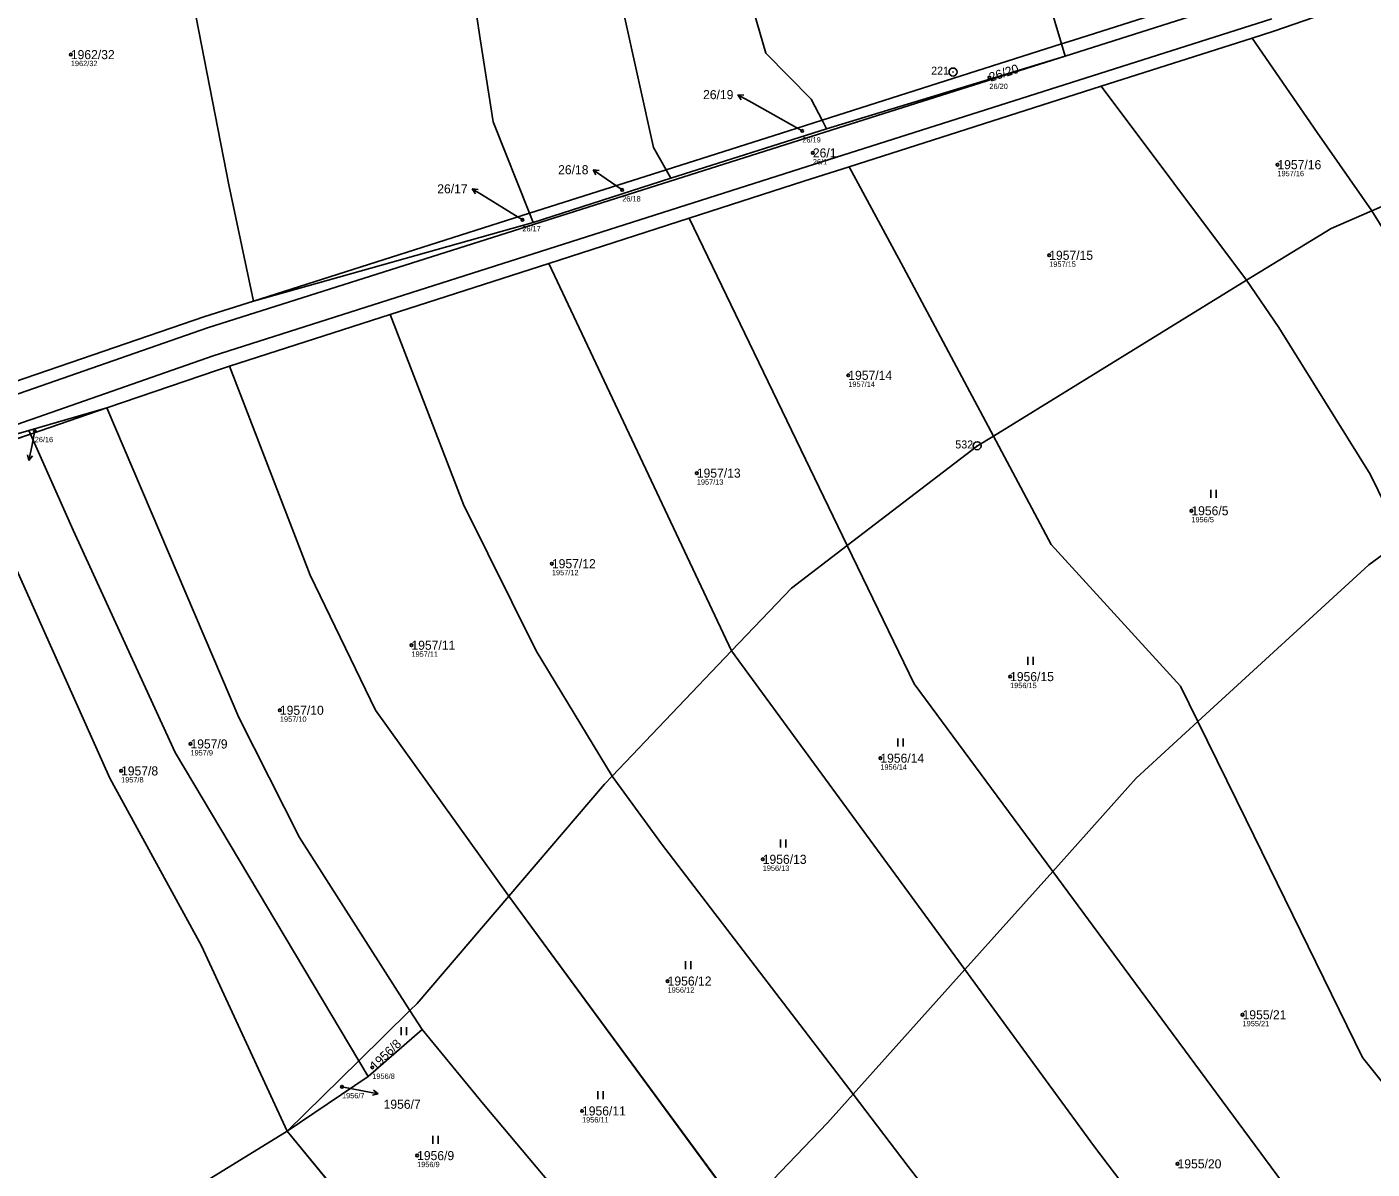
# Model space of a CAD drawing. Extents: x -762274 to -759271, y -1061928 to -1059060.
# Drawn here: x -761526.6 to -761274.4, y -1060598 to -1060383.9 of the extents above; entities that cross this region are included whole.
import ezdxf

# ---------------------------------------------------------------- set-up
doc = ezdxf.new("R2010")
doc.units = 0
for name, color, linetype in [('Definiční body', 7, 'Continuous'), ('Hranice parcel', 7, 'Continuous'), ('Parcelní čísla', 7, 'Continuous'), ('Polygon ku', 7, 'Continuous'), ('Polygon parcely', 7, 'Continuous'), ('Pop  PČ popisy', 7, 'Continuous'), ('Vnitřní kresba', 7, 'Continuous'), ('Značky bodu BP', 7, 'Continuous'), ('Značky kultur', 7, 'Continuous')]:
    doc.layers.add(name, color=color, linetype=linetype)

msp = doc.modelspace()

# ---------------------------------------------------------------- linework, layer by layer
at = {"layer": 'Definiční body'}
for centre in [(-761518.34, -1060389.11), (-761346.14, -1060393.4), (-761381.21, -1060403.42), (-761379.23, -1060407.54), (-761292.14, -1060409.74), (-761414.97, -1060414.48), (-761433.7, -1060420.09), (-761334.92, -1060426.73), (-761372.59, -1060449.23), (-761525.12, -1060459.6), (-761400.99, -1060467.56), (-761308.27, -1060474.62), (-761428.15, -1060484.54), (-761454.49, -1060499.83), (-761342.26, -1060505.71), (-761479.15, -1060512.02), (-761495.92, -1060518.33), (-761366.58, -1060521), (-761508.93, -1060523.39), (-761388.63, -1060539.96), (-761406.46, -1060562.78), (-761298.67, -1060569.1), (-761461.83, -1060578.96), (-761467.51, -1060582.6), (-761422.51, -1060587.13), (-761453.43, -1060595.5), (-761310.86, -1060597.04)]:
    msp.add_circle(centre, 0.25, dxfattribs=at)
at = {"layer": 'Hranice parcel'}
for p, q in [((-761325.18, -1060395.04), (-761296.86, -1060386)), ((-761332.64, -1060387.09), (-761377.52, -1060401.4)), ((-761372.45, -1060410.13), (-761325.18, -1060395.04)), ((-761297.91, -1060431.42), (-761325.18, -1060395.04)), ((-761376.68, -1060403.03), (-761377.52, -1060401.4)), ((-761376.68, -1060403.03), (-761405.87, -1060412.27)), ((-761246.84, -1060406.46), (-761274.47, -1060418.39)), ((-761406.76, -1060410.7), (-761432.38, -1060418.84)), ((-761405.87, -1060412.27), (-761406.76, -1060410.7)), ((-761405.87, -1060412.27), (-761431.68, -1060420.61)), ((-761432.38, -1060418.84), (-761484.13, -1060435.3)), ((-761431.68, -1060420.61), (-761432.38, -1060418.84)), ((-761431.68, -1060420.61), (-761484.13, -1060435.3)), ((-761428.73, -1060428.24), (-761402.43, -1060419.76)), ((-761372.78, -1060481.11), (-761402.43, -1060419.76)), ((-761458.5, -1060437.83), (-761428.73, -1060428.24)), ((-761394.5, -1060500.9), (-761428.73, -1060428.24)), ((-761297.91, -1060431.42), (-761345.39, -1060460.62)), ((-761488.58, -1060447.52), (-761458.5, -1060437.83)), ((-761526.19, -1060459.55), (-761511.57, -1060455.34)), ((-761525.89, -1060460.23), (-761511.57, -1060455.34)), ((-761538.67, -1060463.15), (-761526.19, -1060459.55)), ((-761525.89, -1060460.23), (-761526.19, -1060459.55)), ((-761538.1, -1060464.41), (-761525.89, -1060460.23)), ((-761394.5, -1060500.9), (-761416.86, -1060524.35)), ((-761334.27, -1060542.22), (-761350.76, -1060560.62)), ((-761392.63, -1060606.18), (-761436.24, -1060546.87)), ((-761350.76, -1060560.62), (-761371.7, -1060584)), ((-761454.77, -1060568.31), (-761464.35, -1060577.72)), ((-761452.51, -1060571.84), (-761454.77, -1060568.31)), ((-761462.59, -1060580.67), (-761452.51, -1060571.84)), ((-761464.35, -1060577.72), (-761477.78, -1060590.89)), ((-761462.59, -1060580.67), (-761464.35, -1060577.72)), ((-761477.78, -1060590.89), (-761462.59, -1060580.67)), ((-761523, -1060618.75), (-761477.78, -1060590.89)), ((-761477.78, -1060590.89), (-761452.75, -1060621.37))]:
    msp.add_line(p, q, dxfattribs=at)
for points in [[(-761362.61, -1060303.98), (-761337.24, -1060371.56), (-761332.64, -1060387.09)], [(-761377.52, -1060401.4), (-761379.53, -1060397.49), (-761388.03, -1060388.82), (-761399.3, -1060350.06), (-761408.95, -1060318.37)], [(-761406.76, -1060410.7), (-761409.13, -1060406.55), (-761417.69, -1060367.87), (-761425.29, -1060334.5), (-761428.3, -1060320.92)], [(-761484.13, -1060435.3), (-761488.72, -1060413.55), (-761499.47, -1060358.42), (-761505.75, -1060325.72)], [(-761432.38, -1060418.84), (-761439.17, -1060401.68), (-761441.59, -1060386.18), (-761450.25, -1060328.82), (-761451.14, -1060325.88)], [(-761332.64, -1060387.09), (-761330.38, -1060386.37), (-761302.61, -1060377.52)], [(-761296.86, -1060386), (-761292.81, -1060384.71), (-761272.53, -1060377.65)], [(-761274.47, -1060418.39), (-761284.66, -1060403.7), (-761296.86, -1060386)], [(-761332.64, -1060387.09), (-761331.96, -1060389.38), (-761376.68, -1060403.03)], [(-761377.52, -1060401.4), (-761383.76, -1060403.39), (-761406.76, -1060410.7)], [(-761402.43, -1060419.76), (-761380.95, -1060412.84), (-761372.45, -1060410.13)], [(-761345.39, -1060460.62), (-761362.25, -1060429), (-761372.45, -1060410.13)], [(-761274.47, -1060418.39), (-761282.08, -1060421.68), (-761297.91, -1060431.42)], [(-761246.65, -1060463.98), (-761253.69, -1060451.75), (-761274.47, -1060418.39)], [(-761268.68, -1060480.14), (-761274.76, -1060467.77), (-761291.87, -1060440.27), (-761297.91, -1060431.42)], [(-761484.13, -1060435.3), (-761493.24, -1060438.19), (-761531.09, -1060451.17)], [(-761416.86, -1060524.35), (-761431.13, -1060500.87), (-761444.7, -1060473.47), (-761458.5, -1060437.83)], [(-761511.57, -1060455.34), (-761490.88, -1060448.26), (-761488.58, -1060447.52)], [(-761436.24, -1060546.87), (-761461.2, -1060512.01), (-761473.48, -1060486.69), (-761488.58, -1060447.52)], [(-761454.77, -1060568.31), (-761475.49, -1060535.88), (-761486.82, -1060513.35), (-761511.57, -1060455.34)], [(-761464.35, -1060577.72), (-761498.76, -1060519.96), (-761517.93, -1060478.26), (-761525.89, -1060460.23)], [(-761345.39, -1060460.62), (-761348.35, -1060462.44), (-761372.78, -1060481.11)], [(-761345.39, -1060460.62), (-761334.54, -1060480.95), (-761310.32, -1060507.49), (-761307.05, -1060514.14)], [(-761477.78, -1060590.89), (-761493.84, -1060556.2), (-761511.02, -1060524.76), (-761538.1, -1060464.41)], [(-761372.78, -1060481.11), (-761383.26, -1060489.11), (-761394.5, -1060500.9)], [(-761334.27, -1060542.22), (-761360.24, -1060507.07), (-761372.78, -1060481.11)], [(-761268.68, -1060480.14), (-761275.01, -1060484.78), (-761307.05, -1060514.14)], [(-761350.76, -1060560.62), (-761361.3, -1060546.19), (-761394.5, -1060500.9)], [(-761307.05, -1060514.14), (-761318.62, -1060524.75), (-761334.27, -1060542.22)], [(-761307.05, -1060514.14), (-761298.01, -1060532.54), (-761276.2, -1060577.12), (-761265.28, -1060590.77), (-761260.39, -1060596.89)], [(-761416.86, -1060524.35), (-761418.28, -1060525.85), (-761436.24, -1060546.87)], [(-761371.7, -1060584), (-761407.62, -1060537.03), (-761416.86, -1060524.35)], [(-761276.17, -1060617.86), (-761288.21, -1060604.6), (-761320.85, -1060560.37), (-761334.27, -1060542.22)], [(-761436.24, -1060546.87), (-761453.44, -1060567.01), (-761454.77, -1060568.31)], [(-761291.07, -1060637.45), (-761301.57, -1060626.62), (-761326.45, -1060593.88), (-761350.76, -1060560.62)], [(-761427.51, -1060601.89), (-761440.98, -1060585.86), (-761452.51, -1060571.84)], [(-761371.7, -1060584), (-761376.48, -1060589.33), (-761392.63, -1060606.18)], [(-761310.57, -1060663.1), (-761361.34, -1060597.55), (-761371.7, -1060584)]]:
    msp.add_lwpolyline(points, dxfattribs=at)
at = {"layer": 'Polygon ku'}
msp.add_lwpolyline([(-761842.98, -1060551.47), (-761837.25, -1060550.74), (-761825.78, -1060549.27), (-761803.29, -1060543.28), (-761774.98, -1060535.73), (-761709.41, -1060525.13), (-761690.07, -1060520.8), (-761668.95, -1060513.73), (-761597.93, -1060485.6), (-761588.44, -1060482.32), (-761523.76, -1060617.27), (-761523, -1060618.75), (-761477.78, -1060590.89), (-761452.75, -1060621.37), (-761435.65, -1060642.18), (-761397.03, -1060689.2), (-761389.24, -1060698.69), (-761426.21, -1060752.67)], dxfattribs=at)
at = {"layer": 'Polygon parcely'}
for points in [[(-761302.61, -1060377.52), (-761335.24, -1060297.31), (-761362.61, -1060303.98), (-761337.24, -1060371.56), (-761332.64, -1060387.09), (-761330.38, -1060386.37)], [(-761362.61, -1060303.98), (-761409.45, -1060315.4), (-761408.95, -1060318.37), (-761399.3, -1060350.06), (-761388.03, -1060388.82), (-761379.53, -1060397.49), (-761377.52, -1060401.4), (-761332.64, -1060387.09), (-761337.24, -1060371.56)], [(-761420.69, -1060318.65), (-761428.3, -1060320.92), (-761425.29, -1060334.5), (-761417.69, -1060367.87), (-761409.13, -1060406.55), (-761406.76, -1060410.7), (-761383.76, -1060403.39), (-761377.52, -1060401.4), (-761379.53, -1060397.49), (-761388.03, -1060388.82), (-761399.3, -1060350.06), (-761408.95, -1060318.37)], [(-761417.69, -1060367.87), (-761425.29, -1060334.5), (-761428.3, -1060320.92), (-761434.1, -1060322.65), (-761451.14, -1060325.88), (-761450.25, -1060328.82), (-761441.59, -1060386.18), (-761439.17, -1060401.68), (-761432.38, -1060418.84), (-761406.76, -1060410.7), (-761409.13, -1060406.55)], [(-761488.72, -1060413.55), (-761499.47, -1060358.42), (-761505.75, -1060325.72), (-761506.39, -1060325.86), (-761554.18, -1060336.81), (-761542.84, -1060392.48), (-761531.09, -1060451.17), (-761493.24, -1060438.19), (-761484.13, -1060435.3)], [(-761498.72, -1060324.18), (-761505.75, -1060325.72), (-761499.47, -1060358.42), (-761488.72, -1060413.55), (-761484.13, -1060435.3), (-761432.38, -1060418.84), (-761439.17, -1060401.68), (-761441.59, -1060386.18), (-761450.25, -1060328.82), (-761451.14, -1060325.88), (-761468.12, -1060329.09), (-761491.54, -1060327.88)], [(-761246.84, -1060406.46), (-761272.53, -1060377.65), (-761292.81, -1060384.71), (-761296.86, -1060386), (-761284.66, -1060403.7), (-761274.47, -1060418.39)], [(-761284.66, -1060403.7), (-761296.86, -1060386), (-761325.18, -1060395.04), (-761297.91, -1060431.42), (-761282.08, -1060421.68), (-761274.47, -1060418.39)], [(-761332.64, -1060387.09), (-761377.52, -1060401.4), (-761376.68, -1060403.03), (-761331.96, -1060389.38)], [(-761297.91, -1060431.42), (-761325.18, -1060395.04), (-761372.45, -1060410.13), (-761362.25, -1060429), (-761345.39, -1060460.62)], [(-761406.76, -1060410.7), (-761405.87, -1060412.27), (-761376.68, -1060403.03), (-761377.52, -1060401.4), (-761383.76, -1060403.39)], [(-761244.63, -1060409.46), (-761246.84, -1060406.46), (-761274.47, -1060418.39), (-761253.69, -1060451.75), (-761246.65, -1060463.98), (-761233.1, -1060454.04), (-761223.06, -1060446.53), (-761227.26, -1060439)], [(-761405.87, -1060412.27), (-761406.76, -1060410.7), (-761432.38, -1060418.84), (-761431.68, -1060420.61)], [(-761362.25, -1060429), (-761372.45, -1060410.13), (-761380.95, -1060412.84), (-761402.43, -1060419.76), (-761372.78, -1060481.11), (-761348.35, -1060462.44), (-761345.39, -1060460.62)], [(-761431.68, -1060420.61), (-761432.38, -1060418.84), (-761484.13, -1060435.3)], [(-761282.08, -1060421.68), (-761297.91, -1060431.42), (-761291.87, -1060440.27), (-761274.76, -1060467.77), (-761268.68, -1060480.14), (-761246.65, -1060463.98), (-761253.69, -1060451.75), (-761274.47, -1060418.39)], [(-761372.78, -1060481.11), (-761402.43, -1060419.76), (-761428.73, -1060428.24), (-761394.5, -1060500.9), (-761383.26, -1060489.11)], [(-761394.5, -1060500.9), (-761428.73, -1060428.24), (-761458.5, -1060437.83), (-761444.7, -1060473.47), (-761431.13, -1060500.87), (-761416.86, -1060524.35)], [(-761291.87, -1060440.27), (-761297.91, -1060431.42), (-761345.39, -1060460.62), (-761334.54, -1060480.95), (-761310.32, -1060507.49), (-761307.05, -1060514.14), (-761275.01, -1060484.78), (-761268.68, -1060480.14), (-761274.76, -1060467.77)], [(-761444.7, -1060473.47), (-761458.5, -1060437.83), (-761488.58, -1060447.52), (-761473.48, -1060486.69), (-761461.2, -1060512.01), (-761436.24, -1060546.87), (-761418.28, -1060525.85), (-761416.86, -1060524.35), (-761431.13, -1060500.87)], [(-761473.48, -1060486.69), (-761488.58, -1060447.52), (-761490.88, -1060448.26), (-761511.57, -1060455.34), (-761486.82, -1060513.35), (-761475.49, -1060535.88), (-761454.77, -1060568.31), (-761453.44, -1060567.01), (-761436.24, -1060546.87), (-761461.2, -1060512.01)], [(-761525.89, -1060460.23), (-761511.57, -1060455.34), (-761526.19, -1060459.55)], [(-761486.82, -1060513.35), (-761511.57, -1060455.34), (-761525.89, -1060460.23), (-761517.93, -1060478.26), (-761498.76, -1060519.96), (-761464.35, -1060577.72), (-761454.77, -1060568.31), (-761475.49, -1060535.88)], [(-761525.89, -1060460.23), (-761526.19, -1060459.55), (-761538.67, -1060463.15), (-761538.1, -1060464.41)], [(-761464.35, -1060577.72), (-761498.76, -1060519.96), (-761517.93, -1060478.26), (-761525.89, -1060460.23), (-761538.1, -1060464.41), (-761511.02, -1060524.76), (-761493.84, -1060556.2), (-761477.78, -1060590.89)], [(-761348.35, -1060462.44), (-761372.78, -1060481.11), (-761360.24, -1060507.07), (-761334.27, -1060542.22), (-761318.62, -1060524.75), (-761307.05, -1060514.14), (-761310.32, -1060507.49), (-761334.54, -1060480.95), (-761345.39, -1060460.62)], [(-761538.1, -1060464.41), (-761588.44, -1060482.32), (-761523.76, -1060617.27), (-761523, -1060618.75), (-761477.78, -1060590.89), (-761493.84, -1060556.2), (-761511.02, -1060524.76)], [(-761372.78, -1060481.11), (-761383.26, -1060489.11), (-761394.5, -1060500.9), (-761361.3, -1060546.19), (-761350.76, -1060560.62), (-761334.27, -1060542.22), (-761360.24, -1060507.07)], [(-761275.01, -1060484.78), (-761307.05, -1060514.14), (-761298.01, -1060532.54), (-761276.2, -1060577.12), (-761265.28, -1060590.77), (-761260.39, -1060596.89), (-761255.2, -1060589.71), (-761237.66, -1060565.46), (-761225.6, -1060549.42), (-761225.97, -1060548.93), (-761231.12, -1060542.2), (-761250.91, -1060516.32), (-761268.68, -1060480.14)], [(-761350.76, -1060560.62), (-761361.3, -1060546.19), (-761394.5, -1060500.9), (-761416.86, -1060524.35), (-761407.62, -1060537.03), (-761371.7, -1060584)], [(-761307.05, -1060514.14), (-761318.62, -1060524.75), (-761334.27, -1060542.22), (-761320.85, -1060560.37), (-761288.21, -1060604.6), (-761276.17, -1060617.86), (-761263.67, -1060601.42), (-761260.39, -1060596.89), (-761265.28, -1060590.77), (-761276.2, -1060577.12), (-761298.01, -1060532.54)], [(-761407.62, -1060537.03), (-761416.86, -1060524.35), (-761418.28, -1060525.85), (-761436.24, -1060546.87), (-761392.63, -1060606.18), (-761376.48, -1060589.33), (-761371.7, -1060584)], [(-761288.21, -1060604.6), (-761320.85, -1060560.37), (-761334.27, -1060542.22), (-761350.76, -1060560.62), (-761326.45, -1060593.88), (-761301.57, -1060626.62), (-761291.07, -1060637.45), (-761276.17, -1060617.86)], [(-761392.63, -1060606.18), (-761436.24, -1060546.87), (-761453.44, -1060567.01), (-761454.77, -1060568.31), (-761452.51, -1060571.84), (-761440.98, -1060585.86), (-761427.51, -1060601.89), (-761413.8, -1060619.29), (-761410.99, -1060616.34), (-761407.19, -1060621.37)], [(-761301.57, -1060626.62), (-761326.45, -1060593.88), (-761350.76, -1060560.62), (-761371.7, -1060584), (-761361.34, -1060597.55), (-761310.57, -1060663.1), (-761291.07, -1060637.45)], [(-761452.51, -1060571.84), (-761454.77, -1060568.31), (-761464.35, -1060577.72), (-761462.59, -1060580.67)], [(-761427.51, -1060601.89), (-761440.98, -1060585.86), (-761452.51, -1060571.84), (-761462.59, -1060580.67), (-761477.78, -1060590.89), (-761452.75, -1060621.37), (-761441.29, -1060612.4)], [(-761477.78, -1060590.89), (-761462.59, -1060580.67), (-761464.35, -1060577.72)], [(-761310.57, -1060663.1), (-761361.34, -1060597.55), (-761371.7, -1060584), (-761376.48, -1060589.33), (-761392.63, -1060606.18), (-761382.97, -1060619.31), (-761367.23, -1060640.12), (-761360.72, -1060649.59), (-761330.89, -1060689.83)]]:
    msp.add_lwpolyline(points, close=True, dxfattribs=at)
for points in [[(-761265.99, -1060363.35), (-761276.22, -1060367.49), (-761295.12, -1060375.14), (-761302.61, -1060377.52), (-761330.38, -1060386.37), (-761332.64, -1060387.09), (-761331.96, -1060389.38), (-761376.68, -1060403.03), (-761405.87, -1060412.27), (-761431.68, -1060420.61), (-761484.13, -1060435.3), (-761493.24, -1060438.19), (-761531.09, -1060451.17), (-761592.93, -1060472.36), (-761592.35, -1060473.68), (-761591.85, -1060474.8), (-761590.47, -1060477.92)], [(-761538.67, -1060463.15), (-761526.19, -1060459.55), (-761511.57, -1060455.34), (-761490.88, -1060448.26), (-761488.58, -1060447.52), (-761458.5, -1060437.83), (-761428.73, -1060428.24), (-761402.43, -1060419.76), (-761380.95, -1060412.84), (-761372.45, -1060410.13), (-761325.18, -1060395.04), (-761296.86, -1060386), (-761292.81, -1060384.71), (-761272.53, -1060377.65)]]:
    msp.add_lwpolyline(points, dxfattribs=at)
at = {"layer": 'Pop  PČ popisy'}
for p, q in [((-761390.66, -1060398.09), (-761393.29, -1060396.64)), ((-761393.29, -1060396.64), (-761392.17, -1060396.68)), ((-761393.29, -1060396.64), (-761392.65, -1060397.56)), ((-761381.21, -1060403.42), (-761390.66, -1060398.09)), ((-761417.97, -1060412.4), (-761420.43, -1060410.68)), ((-761420.43, -1060410.68), (-761419.32, -1060410.84)), ((-761420.43, -1060410.68), (-761419.9, -1060411.66)), ((-761440.55, -1060415.85), (-761443.09, -1060414.26)), ((-761443.09, -1060414.26), (-761441.98, -1060414.37)), ((-761443.09, -1060414.26), (-761442.51, -1060415.22)), ((-761414.97, -1060414.48), (-761417.97, -1060412.4)), ((-761433.7, -1060420.09), (-761440.55, -1060415.85)), ((-761525.12, -1060459.6), (-761525.62, -1060462.26)), ((-761525.62, -1060462.26), (-761526.19, -1060465.21)), ((-761526.19, -1060465.21), (-761526.49, -1060464.13)), ((-761526.19, -1060465.21), (-761525.51, -1060464.32)), ((-761467.51, -1060582.6), (-761463.66, -1060583.33)), ((-761463.66, -1060583.33), (-761460.71, -1060583.9)), ((-761460.71, -1060583.9), (-761461.6, -1060583.22)), ((-761460.71, -1060583.9), (-761461.79, -1060584.2))]:
    msp.add_line(p, q, dxfattribs=at)
at = {"layer": 'Vnitřní kresba'}
for p, q in [((-761331.96, -1060389.38), (-761294.41, -1060377.47)), ((-761293.2, -1060382.38), (-761381.7, -1060410.53)), ((-761383.09, -1060405.6), (-761331.96, -1060389.38)), ((-761492.71, -1060440.31), (-761383.09, -1060405.6)), ((-761381.7, -1060410.53), (-761491.65, -1060445.55)), ((-761591.85, -1060474.8), (-761492.71, -1060440.31)), ((-761556.15, -1060468.14), (-761491.65, -1060445.55))]:
    msp.add_line(p, q, dxfattribs=at)
at = {"layer": 'Značky bodu BP'}
for centre, radius in [((-761352.96, -1060392.37), 0.75), ((-761352.96, -1060392.37), 0.03), ((-761348.43, -1060462.44), 0.75), ((-761348.43, -1060462.44), 0.03)]:
    msp.add_circle(centre, radius, dxfattribs=at)
at = {"layer": 'Značky kultur'}
for p, q in [((-761304.64, -1060472.19), (-761304.64, -1060470.69)), ((-761303.64, -1060472.19), (-761303.64, -1060470.69)), ((-761338.96, -1060503.51), (-761338.96, -1060502.01)), ((-761337.96, -1060503.51), (-761337.96, -1060502.01)), ((-761363.32, -1060518.8), (-761363.32, -1060517.3)), ((-761362.32, -1060518.8), (-761362.32, -1060517.3)), ((-761385.29, -1060537.76), (-761385.29, -1060536.26)), ((-761384.29, -1060537.76), (-761384.29, -1060536.26)), ((-761403.13, -1060560.58), (-761403.13, -1060559.08)), ((-761402.13, -1060560.58), (-761402.13, -1060559.08)), ((-761456.43, -1060572.94), (-761456.43, -1060571.44)), ((-761455.43, -1060572.94), (-761455.43, -1060571.44)), ((-761419.56, -1060584.93), (-761419.56, -1060583.43)), ((-761418.56, -1060584.93), (-761418.56, -1060583.43)), ((-761450.47, -1060593.3), (-761450.47, -1060591.8)), ((-761449.47, -1060593.3), (-761449.47, -1060591.8))]:
    msp.add_line(p, q, dxfattribs=at)

# ---------------------------------------------------------------- texts
at = {"layer": 'Definiční body'}
for s, p in [('1962/32', (-761518.34, -1060391.27)), ('26/20', (-761346.14, -1060395.56)), ('26/19', (-761381.21, -1060405.58)), ('26/1', (-761379.23, -1060409.7)), ('1957/16', (-761292.14, -1060411.9)), ('26/18', (-761414.97, -1060416.64)), ('26/17', (-761433.7, -1060422.25)), ('1957/15', (-761334.92, -1060428.89)), ('1957/14', (-761372.59, -1060451.39)), ('26/16', (-761525.12, -1060461.76)), ('1957/13', (-761400.99, -1060469.72)), ('1956/5', (-761308.27, -1060476.78)), ('1957/12', (-761428.15, -1060486.7)), ('1957/11', (-761454.49, -1060501.99)), ('1956/15', (-761342.26, -1060507.87)), ('1957/10', (-761479.15, -1060514.18)), ('1957/9', (-761495.92, -1060520.49)), ('1956/14', (-761366.58, -1060523.16)), ('1957/8', (-761508.93, -1060525.55)), ('1956/13', (-761388.63, -1060542.12)), ('1956/12', (-761406.46, -1060564.94)), ('1955/21', (-761298.67, -1060571.26)), ('1956/8', (-761461.83, -1060581.12)), ('1956/7', (-761467.51, -1060584.76)), ('1956/11', (-761422.51, -1060589.29)), ('1956/9', (-761453.43, -1060597.66))]:
    msp.add_text(s, height=1, dxfattribs=at).set_placement(p)
at = {"layer": 'Parcelní čísla'}
for s, p in [('1962/32', (-761518.34, -1060389.96)), ('26/19', (-761399.82, -1060397.46)), ('26/1', (-761379.23, -1060408.39)), ('1957/16', (-761292.14, -1060410.59)), ('26/18', (-761426.99, -1060411.54)), ('26/17', (-761449.65, -1060415.12)), ('1957/15', (-761334.92, -1060427.58)), ('1957/14', (-761372.59, -1060450.08)), ('1957/13', (-761400.99, -1060468.41)), ('1956/5', (-761308.27, -1060475.47)), ('1957/12', (-761428.15, -1060485.39)), ('1957/11', (-761454.49, -1060500.68)), ('1956/15', (-761342.26, -1060506.56)), ('1957/10', (-761479.15, -1060512.87)), ('1957/9', (-761495.92, -1060519.18)), ('1956/14', (-761366.58, -1060521.85)), ('1957/8', (-761508.93, -1060524.24)), ('1956/13', (-761388.63, -1060540.81)), ('1956/12', (-761406.46, -1060563.63)), ('1955/21', (-761298.67, -1060569.95)), ('1956/7', (-761459.71, -1060586.72)), ('1956/11', (-761422.51, -1060587.98)), ('1956/9', (-761453.43, -1060596.35)), ('1955/20', (-761310.86, -1060597.89))]:
    msp.add_text(s, height=1.7, dxfattribs=at).set_placement(p)
for s, rotation, p in [('26/20', 18, (-761345.88, -1060394.21)), ('1956/8', 44, (-761461.24, -1060579.57))]:
    msp.add_text(s, height=1.7, rotation=rotation, dxfattribs=at).set_placement(p)
at = {"layer": 'Značky bodu BP'}
for s, p in [('221', (-761357.06, -1060392.87)), ('532', (-761352.53, -1060462.94))]:
    msp.add_text(s, height=1.5, dxfattribs=at).set_placement(p)

doc.saveas('drawing.dxf')
